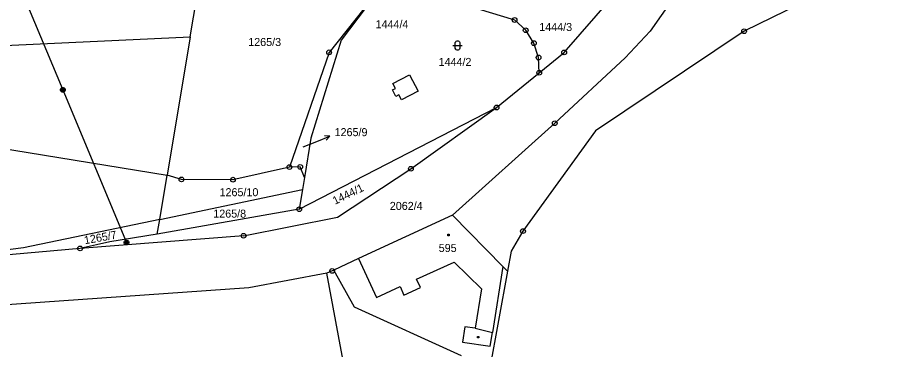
# Model space of a CAD drawing. Extents: x -795483 to -789093, y -1112258 to -1108741.
# Drawn here: x -792510.5 to -792326, y -1110161.2 to -1110090.9 of the extents above; entities that cross this region are included whole.
import ezdxf

# ---------------------------------------------------------------- set-up
doc = ezdxf.new("R2010")
doc.units = 0
for name, color, linetype in [('Komunikace', 7, 'Continuous'), ('Vrstva 1', 7, 'Continuous'), ('Vrstva 10', 7, 'Continuous'), ('Vrstva 12', 7, 'Continuous'), ('Vrstva 14', 7, 'Continuous'), ('Vrstva 15', 7, 'Continuous'), ('Vrstva 16', 7, 'Continuous'), ('Vrstva 2', 7, 'Continuous'), ('Vrstva 23', 7, 'Continuous'), ('Vrstva 25', 7, 'Continuous'), ('Vrstva 26', 7, 'Continuous'), ('Vrstva 28', 7, 'Continuous')]:
    doc.layers.add(name, color=color, linetype=linetype)

msp = doc.modelspace()

# ---------------------------------------------------------------- linework, layer by layer
at = {"layer": 'Komunikace'}
msp.add_line((-792450.05, -1110118.28), (-792447.21, -1110117.15), dxfattribs=at)
at = {"layer": 'Vrstva 1'}
for p, q in [((-792473.97, -1110095.05), (-792469.85, -1110071.05)), ((-792309.21, -1110070.53), (-792356.78, -1110093.85)), ((-792432.45, -1110083.04), (-792444.57, -1110098.32)), ((-792432.45, -1110083.04), (-792442.06, -1110095.73)), ((-792426.19, -1110084.99), (-792405.33, -1110091.48)), ((-792394.85, -1110098.34), (-792383.46, -1110085.31)), ((-792371.97, -1110087.16), (-792376.65, -1110093.83)), ((-792402.99, -1110093.65), (-792405.33, -1110091.48)), ((-792356.78, -1110093.85), (-792388.21, -1110114.91)), ((-792376.65, -1110093.83), (-792381.92, -1110099.45)), ((-792544.91, -1110098.39), (-792473.97, -1110095.05)), ((-792473.97, -1110095.05), (-792478.86, -1110124.3)), ((-792442.06, -1110095.73), (-792448.48, -1110116.49)), ((-792444.57, -1110098.32), (-792452.97, -1110122.58)), ((-792400.13, -1110102.64), (-792394.85, -1110098.34)), ((-792381.92, -1110099.45), (-792396.85, -1110113.31)), ((-792409.14, -1110109.98), (-792400.13, -1110102.64)), ((-792450.89, -1110131.49), (-792409.14, -1110109.98)), ((-792427.28, -1110122.94), (-792409.14, -1110109.98)), ((-792396.85, -1110113.31), (-792418.44, -1110132.75)), ((-792388.21, -1110114.91), (-792403.56, -1110136.12)), ((-792521.63, -1110117.28), (-792478.86, -1110124.3)), ((-792448.48, -1110116.49), (-792449.81, -1110124.79)), ((-792452.97, -1110122.58), (-792464.92, -1110125.24)), ((-792450.69, -1110122.53), (-792452.97, -1110122.58)), ((-792449.81, -1110124.79), (-792450.69, -1110122.53)), ((-792442.81, -1110133.17), (-792427.28, -1110122.94)), ((-792480.42, -1110133.64), (-792478.86, -1110124.3)), ((-792475.82, -1110125.19), (-792478.86, -1110124.3)), ((-792464.92, -1110125.24), (-792475.82, -1110125.19)), ((-792449.81, -1110124.79), (-792450.22, -1110127.31)), ((-792480.42, -1110133.64), (-792450.22, -1110127.31)), ((-792450.22, -1110127.31), (-792450.89, -1110131.49)), ((-792450.89, -1110131.49), (-792480.94, -1110136.77)), ((-792418.44, -1110132.75), (-792438.36, -1110141.93)), ((-792418.44, -1110132.75), (-792407.86, -1110143.58)), ((-792480.42, -1110133.64), (-792509.25, -1110139.68)), ((-792480.94, -1110136.77), (-792480.42, -1110133.64)), ((-792462.68, -1110137.11), (-792442.81, -1110133.17)), ((-792403.56, -1110136.12), (-792406.08, -1110140.32)), ((-792462.68, -1110137.11), (-792497.25, -1110139.78)), ((-792480.94, -1110136.77), (-792490.97, -1110138.39)), ((-792509.25, -1110139.68), (-792542.21, -1110143.85)), ((-792497.25, -1110139.78), (-792542.21, -1110143.85)), ((-792490.97, -1110138.39), (-792497.25, -1110139.78)), ((-792438.36, -1110141.93), (-792443.61, -1110144.37)), ((-792406.08, -1110140.32), (-792406.86, -1110144.6)), ((-792407.86, -1110143.58), (-792406.86, -1110144.6)), ((-792445.06, -1110144.98), (-792461.57, -1110148.1)), ((-792443.93, -1110144.52), (-792445.06, -1110144.98)), ((-792440.37, -1110170.05), (-792445.06, -1110144.98)), ((-792443.61, -1110144.37), (-792443.93, -1110144.52)), ((-792439.23, -1110152.21), (-792443.61, -1110144.37)), ((-792406.86, -1110144.6), (-792414.59, -1110187.07)), ((-792461.57, -1110148.1), (-792538.81, -1110153.52)), ((-792416.55, -1110162.51), (-792439.23, -1110152.21))]:
    msp.add_line(p, q, dxfattribs=at)
msp.add_lwpolyline([(-792400.13, -1110102.64), (-792400.27, -1110099.41), (-792401.26, -1110096.38), (-792402.99, -1110093.65)], dxfattribs=at)
at = {"layer": 'Vrstva 10'}
msp.add_arc((-792225.58, -1110307.18), 393.52, 135.381, 155.7424, dxfattribs=at)
at = {"layer": 'Vrstva 12'}
for p, q in [((-792519.64, -1110061.42), (-792500.93, -1110106.24)), ((-792500.93, -1110106.24), (-792487.44, -1110138.53))]:
    msp.add_line(p, q, dxfattribs=at)
at = {"layer": 'Vrstva 16'}
for p, q in [((-792447.21, -1110117.15), (-792444.42, -1110116.04)), ((-792444.42, -1110116.04), (-792445.54, -1110115.95)), ((-792444.42, -1110116.04), (-792445.17, -1110116.88))]:
    msp.add_line(p, q, dxfattribs=at)
at = {"layer": 'Vrstva 2'}
for p, q in [((-792431.11, -1110104.88), (-792427.57, -1110103.04)), ((-792427.57, -1110103.04), (-792425.75, -1110106.53)), ((-792430.56, -1110105.93), (-792431.11, -1110104.88)), ((-792431.18, -1110106.25), (-792430.56, -1110105.93)), ((-792430.46, -1110107.63), (-792431.18, -1110106.25)), ((-792425.75, -1110106.53), (-792429.29, -1110108.38)), ((-792429.85, -1110107.31), (-792430.46, -1110107.63)), ((-792429.29, -1110108.38), (-792429.85, -1110107.31)), ((-792438.36, -1110141.93), (-792434.58, -1110150.12)), ((-792426.07, -1110146.25), (-792418.15, -1110142.65)), ((-792418.15, -1110142.65), (-792412.31, -1110148.35)), ((-792407.86, -1110143.58), (-792410.04, -1110157.58)), ((-792425.24, -1110148.07), (-792426.07, -1110146.25)), ((-792434.58, -1110150.12), (-792429.57, -1110147.84)), ((-792429.57, -1110147.84), (-792428.75, -1110149.66)), ((-792428.75, -1110149.66), (-792425.24, -1110148.07)), ((-792412.31, -1110148.35), (-792413.65, -1110156.64)), ((-792415.88, -1110156.32), (-792416.36, -1110159.62)), ((-792413.65, -1110156.64), (-792415.88, -1110156.32)), ((-792413.65, -1110156.64), (-792410.04, -1110157.58)), ((-792410.49, -1110160.47), (-792410.04, -1110157.58)), ((-792416.36, -1110159.62), (-792410.49, -1110160.47))]:
    msp.add_line(p, q, dxfattribs=at)
at = {"layer": 'Vrstva 23'}
for p, q in [((-792417.7, -1110095.97), (-792417.5, -1110095.87)), ((-792417.5, -1110095.87), (-792417.3, -1110095.87)), ((-792417.3, -1110095.87), (-792417.1, -1110095.97)), ((-792418.4, -1110096.87), (-792416.4, -1110096.87)), ((-792417.9, -1110096.27), (-792417.8, -1110096.07)), ((-792417.9, -1110097.47), (-792417.9, -1110096.27)), ((-792417.8, -1110097.67), (-792417.9, -1110097.47)), ((-792417.8, -1110096.07), (-792417.7, -1110095.97)), ((-792417.7, -1110097.77), (-792417.8, -1110097.67)), ((-792417.5, -1110097.87), (-792417.7, -1110097.77)), ((-792417.1, -1110097.77), (-792417.3, -1110097.87)), ((-792417.1, -1110095.97), (-792417, -1110096.07)), ((-792417, -1110097.67), (-792417.1, -1110097.77)), ((-792417, -1110096.07), (-792416.9, -1110096.27)), ((-792416.9, -1110097.47), (-792417, -1110097.67)), ((-792416.9, -1110096.27), (-792416.9, -1110097.47)), ((-792417.3, -1110097.87), (-792417.5, -1110097.87))]:
    msp.add_line(p, q, dxfattribs=at)
at = {"layer": 'Vrstva 25'}
for p, q in [((-792419.48, -1110136.78), (-792419.18, -1110136.78)), ((-792419.48, -1110137.08), (-792419.48, -1110136.78)), ((-792419.18, -1110137.08), (-792419.48, -1110137.08)), ((-792419.18, -1110136.78), (-792419.18, -1110137.08)), ((-792413.21, -1110158.38), (-792412.91, -1110158.38)), ((-792413.21, -1110158.68), (-792413.21, -1110158.38)), ((-792412.91, -1110158.68), (-792413.21, -1110158.68)), ((-792412.91, -1110158.38), (-792412.91, -1110158.68))]:
    msp.add_line(p, q, dxfattribs=at)
at = {"layer": 'Vrstva 26'}
for p, q in [((-792501.43, -1110106.14), (-792501.33, -1110105.94)), ((-792501.43, -1110106.34), (-792501.43, -1110106.14)), ((-792501.33, -1110106.54), (-792501.43, -1110106.34)), ((-792501.33, -1110105.94), (-792501.23, -1110105.84)), ((-792501.23, -1110106.64), (-792501.33, -1110106.54)), ((-792501.23, -1110105.84), (-792501.03, -1110105.74)), ((-792501.23, -1110106.04), (-792501.23, -1110106.44)), ((-792501.23, -1110106.44), (-792501.03, -1110106.54)), ((-792501.03, -1110106.74), (-792501.23, -1110106.64)), ((-792501.03, -1110105.74), (-792500.83, -1110105.74)), ((-792501.03, -1110106.54), (-792501.03, -1110105.94)), ((-792501.03, -1110105.94), (-792500.83, -1110105.94)), ((-792500.83, -1110106.74), (-792501.03, -1110106.74)), ((-792500.83, -1110105.74), (-792500.63, -1110105.84)), ((-792500.83, -1110105.94), (-792500.83, -1110106.54)), ((-792500.83, -1110106.54), (-792500.63, -1110106.44)), ((-792500.63, -1110106.64), (-792500.83, -1110106.74)), ((-792500.63, -1110105.84), (-792500.53, -1110105.94)), ((-792500.63, -1110106.44), (-792500.63, -1110106.04)), ((-792500.53, -1110106.54), (-792500.63, -1110106.64)), ((-792500.53, -1110105.94), (-792500.43, -1110106.14)), ((-792500.43, -1110106.34), (-792500.53, -1110106.54)), ((-792500.43, -1110106.14), (-792500.43, -1110106.34)), ((-792487.94, -1110138.43), (-792487.84, -1110138.23)), ((-792487.84, -1110138.23), (-792487.74, -1110138.13)), ((-792487.74, -1110138.13), (-792487.54, -1110138.03)), ((-792487.74, -1110138.33), (-792487.74, -1110138.73)), ((-792487.54, -1110138.03), (-792487.34, -1110138.03)), ((-792487.54, -1110138.83), (-792487.54, -1110138.23)), ((-792487.54, -1110138.23), (-792487.34, -1110138.23)), ((-792487.34, -1110138.03), (-792487.14, -1110138.13)), ((-792487.34, -1110138.23), (-792487.34, -1110138.83)), ((-792487.14, -1110138.13), (-792487.04, -1110138.23)), ((-792487.14, -1110138.73), (-792487.14, -1110138.33)), ((-792487.04, -1110138.23), (-792486.94, -1110138.43)), ((-792487.94, -1110138.63), (-792487.94, -1110138.43)), ((-792487.84, -1110138.83), (-792487.94, -1110138.63)), ((-792487.74, -1110138.93), (-792487.84, -1110138.83)), ((-792487.74, -1110138.73), (-792487.54, -1110138.83)), ((-792487.54, -1110139.03), (-792487.74, -1110138.93)), ((-792487.34, -1110139.03), (-792487.54, -1110139.03)), ((-792487.34, -1110138.83), (-792487.14, -1110138.73)), ((-792487.14, -1110138.93), (-792487.34, -1110139.03)), ((-792487.04, -1110138.83), (-792487.14, -1110138.93)), ((-792486.94, -1110138.63), (-792487.04, -1110138.83)), ((-792486.94, -1110138.43), (-792486.94, -1110138.63))]:
    msp.add_line(p, q, dxfattribs=at)
at = {"layer": 'Vrstva 28'}
for centre, radius in [((-792405.33, -1110091.48), 0.5), ((-792405.33, -1110091.48), 0.01), ((-792402.99, -1110093.65), 0.5), ((-792402.99, -1110093.65), 0.01), ((-792356.78, -1110093.85), 0.5), ((-792356.78, -1110093.85), 0.01), ((-792401.26, -1110096.38), 0.5), ((-792401.26, -1110096.38), 0.01), ((-792444.57, -1110098.32), 0.5), ((-792444.57, -1110098.32), 0.01), ((-792400.27, -1110099.41), 0.5), ((-792400.27, -1110099.41), 0.01), ((-792394.85, -1110098.34), 0.5), ((-792394.85, -1110098.34), 0.01), ((-792400.13, -1110102.64), 0.5), ((-792400.13, -1110102.64), 0.01), ((-792409.14, -1110109.98), 0.5), ((-792409.14, -1110109.98), 0.01), ((-792396.85, -1110113.31), 0.5), ((-792396.85, -1110113.31), 0.01), ((-792452.97, -1110122.58), 0.5), ((-792452.97, -1110122.58), 0.01), ((-792450.69, -1110122.53), 0.5), ((-792450.69, -1110122.53), 0.01), ((-792427.28, -1110122.94), 0.5), ((-792427.28, -1110122.94), 0.01), ((-792475.82, -1110125.19), 0.5), ((-792475.82, -1110125.19), 0.01), ((-792464.92, -1110125.24), 0.5), ((-792464.92, -1110125.24), 0.01), ((-792450.89, -1110131.49), 0.5), ((-792450.89, -1110131.49), 0.01), ((-792403.56, -1110136.12), 0.5), ((-792403.56, -1110136.12), 0.01), ((-792462.68, -1110137.11), 0.5), ((-792462.68, -1110137.11), 0.01), ((-792497.25, -1110139.78), 0.5), ((-792497.25, -1110139.78), 0.01), ((-792443.93, -1110144.52), 0.5), ((-792443.93, -1110144.52), 0.01)]:
    msp.add_circle(centre, radius, dxfattribs=at)

# ---------------------------------------------------------------- texts
at = {"layer": 'Vrstva 14'}
for s, height, p in [('1444/3', 1.7, (-792400.12, -1110093.81)), ('1265/3', 1.7, (-792461.69, -1110096.98)), ('1444/2', 1.7, (-792421.42, -1110101.2)), ('1265/9', 0.1, (-792450.05, -1110118.28)), ('1265/10', 1.7, (-792467.76, -1110128.74)), ('2062/4', 1.7, (-792431.74, -1110131.64)), ('1265/8', 1.7, (-792469.09, -1110133.27))]:
    msp.add_text(s, height=height, dxfattribs=at).set_placement(p)
for s, rotation, p in [('1444/1', 25.7415, (-792443.34, -1110130.57)), ('1265/7', 10.0512, (-792496.26, -1110138.9))]:
    msp.add_text(s, height=1.7, rotation=rotation, dxfattribs=at).set_placement(p)
at = {"layer": 'Vrstva 15'}
msp.add_text('595', height=1.7, dxfattribs=at).set_placement((-792421.39, -1110140.53))
at = {"layer": 'Vrstva 16'}
for s, p in [('1444/4', (-792434.75, -1110093.22)), ('1265/9', (-792443.42, -1110116.04))]:
    msp.add_text(s, height=1.7, dxfattribs=at).set_placement(p)

doc.saveas('drawing.dxf')
